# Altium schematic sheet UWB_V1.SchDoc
size B
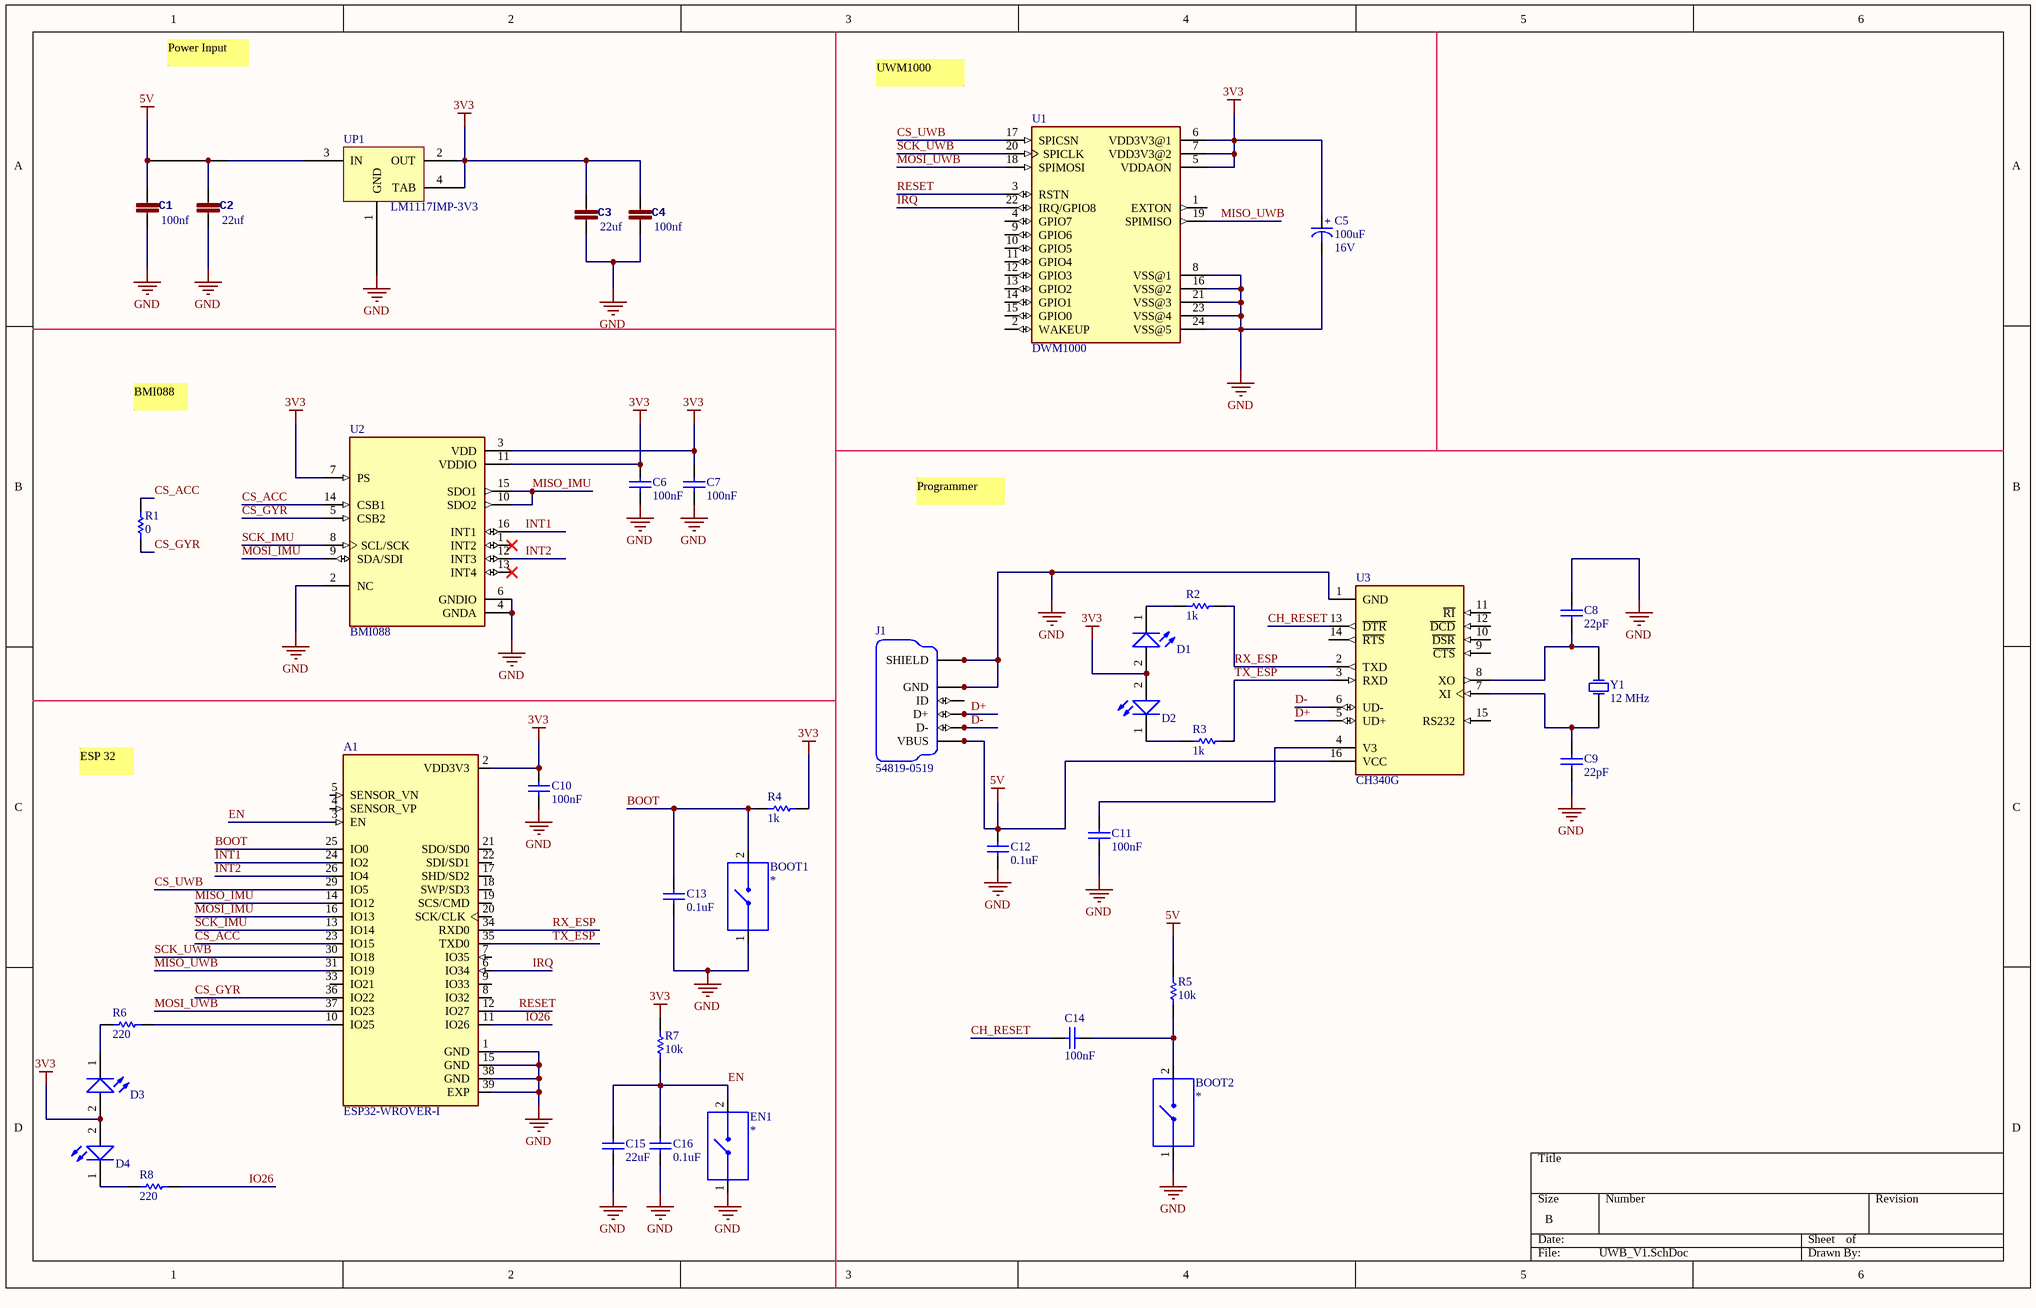
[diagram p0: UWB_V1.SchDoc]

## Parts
A1  ESP32-WROVER-I  [XCVR_ESP32-WROVER-I]
BOOT1  1437566-4  [SW_TS09-63-25-R-160-SMT-TR]  (value not drawn)
BOOT2  1437566-4  [SW_TS09-63-25-R-160-SMT-TR]  (value not drawn)
C1  value 100nf  [C_805]  (hidden comment: Cap)
C2  value 22uf  [C_805]  (hidden comment: Cap)
C3  value 22uf  [C_805]  (hidden comment: Cap)
C4  value 100nf  [C_805]  (hidden comment: Cap)
C5  Voltage: 16V  [cap 02]  (hidden comment: 100uF)
C6  100nF  [C_805]
C7  100nF  [C_805]
C8  22pF  [C_805]
C9  22pF  [C_805]
C10  100nF  [C_805]
C11  100nF  [C_805]
C12  0.1uF  [C_805]
C13  0.1uF  [C_805]
C14  100nF  [C_805]
C15  22uF  [C_805]
C16  0.1uF  [C_805]
D1  LED SMD PACKAGE  [LEDC2012X120N]  (value not drawn)
D2  LED SMD PACKAGE  [LEDC2012X120N]  (value not drawn)
D3  LED SMD PACKAGE  [LEDC2012X120N]  (value not drawn)
D4  LED SMD PACKAGE  [LEDC2012X120N]  (value not drawn)
EN1  1437566-4  [SW_TS09-63-25-R-160-SMT-TR]  (value not drawn)
J1  54819-0519  [MOLEX_54819-0519]
R1  value 0  [R_805]  (hidden comment: Resistor SMD 0603)
R2  value 1k  [R_805]  (hidden comment: Resistor SMD 0603)
R3  value 1k  [R_805]  (hidden comment: Resistor SMD 0603)
R4  value 1k  [R_805]  (hidden comment: Resistor SMD 0603)
R5  value 10k  [R_805]  (hidden comment: Resistor SMD 0603)
R6  value 220  [R_805]  (hidden comment: Resistor SMD 0603)
R7  value 10k  [R_805]  (hidden comment: Resistor SMD 0603)
R8  value 220  [R_805]  (hidden comment: Resistor SMD 0603)
U1  DWM1000  [XCVR_DWM1000]
U2  BMI088  [PQFN50P450X300X100-16N]
U3  CH340G  [SOIC127P600X180-16N]
UP1  LM1117IMP-3V3  [SOT223_4]
Y1  12 MHz  [Crystal SMD]

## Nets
3V3: A1.2(VDD3V3) C3.1 C4.1 C5.1(+) C6.2 C7.2 C10.2 D1.2(A) D2.2(A) D3.2(A) D4.2(A) R4.1 R7.1 U1.5(VDDAON) U1.6(VDD3V3@1) U1.7(VDD3V3@2) U2.3(VDD) U2.7(PS) U2.11(VDDIO) UP1.2(OUT) UP1.4(TAB)
5V: C1.1 C2.1 C12.1 J1.1(VBUS) J1.6(VBUS) R5.1 U3.16(VCC) UP1.3(IN)
GND: A1.1(GND) A1.15(GND) A1.38(GND) A1.39(EXP) BOOT1.1 BOOT2.1 C1.2 C2.2 C3.2 C4.2 C5.2(-) C6.1 C7.1 C8.1 C9.2 C10.1 C11.2 C12.2 C13.1 C15.1 C16.1 EN1.1 J1.5(GND) J1.10(GND) J1.11(SHIELD) J1.12(SHIELD) J1.S1(SHIELD) J1.S2(SHIELD) U1.8(VSS@1) U1.16(VSS@2) U1.21(VSS@3) U1.23(VSS@4) U1.24(VSS@5) U2.2(NC) U2.4(GNDA) U2.6(GNDIO) U3.1(GND) UP1.1(GND)
BOOT: A1.25(IO0) BOOT1.2 C13.2 R4.2
CH_RESET: C14.2 U3.13(~{DTR})
CS_ACC: A1.23(IO15) R1.2 U2.14(CSB1)
CS_GYR: A1.36(IO22) R1.1 U2.5(CSB2)
CS_UWB: A1.29(IO5) U1.17(SPICSN)
D+: J1.3(D+) J1.8(D+) U3.5(UD+)
D-: J1.2(D-) J1.7(D-) U3.6(UD-)
EN: A1.3(EN) C15.2 C16.2 EN1.2 R7.2
INT1: A1.24(IO2) U2.16(INT1)
INT2: A1.26(IO4) U2.12(INT3)
IO26: A1.11(IO26) R8.1
IRQ: A1.6(IO34) U1.22(IRQ/GPIO8)
MISO_IMU: A1.14(IO12) U2.10(SDO2) U2.15(SDO1)
MISO_UWB: A1.31(IO19) U1.19(SPIMISO)
MOSI_IMU: A1.16(IO13) U2.9(SDA/SDI)
MOSI_UWB: A1.37(IO23) U1.18(SPIMOSI)
RESET: A1.12(IO27) U1.3(RSTN)
RX_ESP: A1.34(RXD0) R2.2 U3.2(TXD)
SCK_IMU: A1.13(IO14) U2.8(SCL/SCK)
SCK_UWB: A1.30(IO18) U1.20(SPICLK)
TX_ESP: A1.35(TXD0) R3.2 U3.3(RXD)
NetA1_10: A1.10(IO25) R6.1
NetBOOT2_2: BOOT2.2 C14.1 R5.2
NetC8_2: C8.2 U3.8(XO) Y1.2(OSC2)
NetC9_1: C9.1 U3.7(XI) Y1.1(OSC1)
NetC11_1: C11.1 U3.4(V3)
NetD1_1: D1.1(K) R2.1
NetD2_1: D2.1(K) R3.1
NetD3_1: D3.1(K) R6.2
NetD4_1: D4.1(K) R8.2
NetJ1_4: J1.4(ID) J1.9(ID)

Not connected (* = marked no-connect by the designer): A1 4(SENSOR_VP) 5(SENSOR_VN) 7(IO35) 8(IO32) 9(IO33) 17(SHD/SD2) 18(SWP/SD3) 19(SCS/CMD) 20(SCK/CLK) 21(SDO/SD0) 22(SDI/SD1) 33(IO21); U1 1(EXTON) 2(WAKEUP) 4(GPIO7) 9(GPIO6) 10(GPIO5) 11(GPIO4) 12(GPIO3) 13(GPIO2) 14(GPIO1) 15(GPIO0); U2 1(INT2)* 13(INT4)*; U3 9(~{CTS}) 10(~{DSR}) 11(~{RI}) 12(~{DCD}) 14(~{RTS}) 15(RS232)

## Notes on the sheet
- Power Input
- UWM1000
- BMI088
- Programmer
- ESP 32

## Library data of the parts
A1 = ESP32-WROVER-I: Module: combo; GPIO, I2C x2, I2S x2, SDIO, SPI x3, UART x3; U.FL
BOOT1 BOOT2 EN1 = 1437566-4: Switch Tactile OFF _ON_ SPST Rectangular Button Gull Wing 0.05A 12VDC 1.77N SMD T/R; MF: TE Connectivity; Configuration_Pole-Throw: Single Pole - Single Throw; Contact_Current_Rating: 50 mA; MP: FSMSMTR
C1-C4 = Cap_1
C5 = Cap-Polar: Polar Capacitor; Designer: Saeid Jorablo; Organazation: ControTec
C6-C16 = CAP SMD 0805: CAP 0805; Designer: Abbas Basereh
D1-D4 = LED SMD PACKAGE: SMD Mono-color Chip LED Waterclear; Part Number: 150080BS75000; Peak Wavelength: 465 nm; Forward Voltage: 3.2 V
J1 = 54819-0519: USB - mini B USB 2.0 OTG Receptacle Connector 5 Position Through Hole, Right Angle; MF: Molex
U1 = DWM1000: 802.15.4 IR-UWB Transceiver Module 3.5GHz ~ 6.5GHz Integrated, Chip Surface Mount; MF: Decawave Limited
U2 = BMI088: Accelerometer, Gyroscope, 6 Axis Sensor IÂ²C, SPI Output; MF: Bosch Sensortec
UP1 = LM1117IMP-x.x: x.x Volt, 800mA Low-Dropout Linear Regulator, 4-pin SOT-223; Designer: Abbas Basereh
Y1 = XTAL_Crystal: XTAL Crystal; Designer: ABBAS BASEREH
